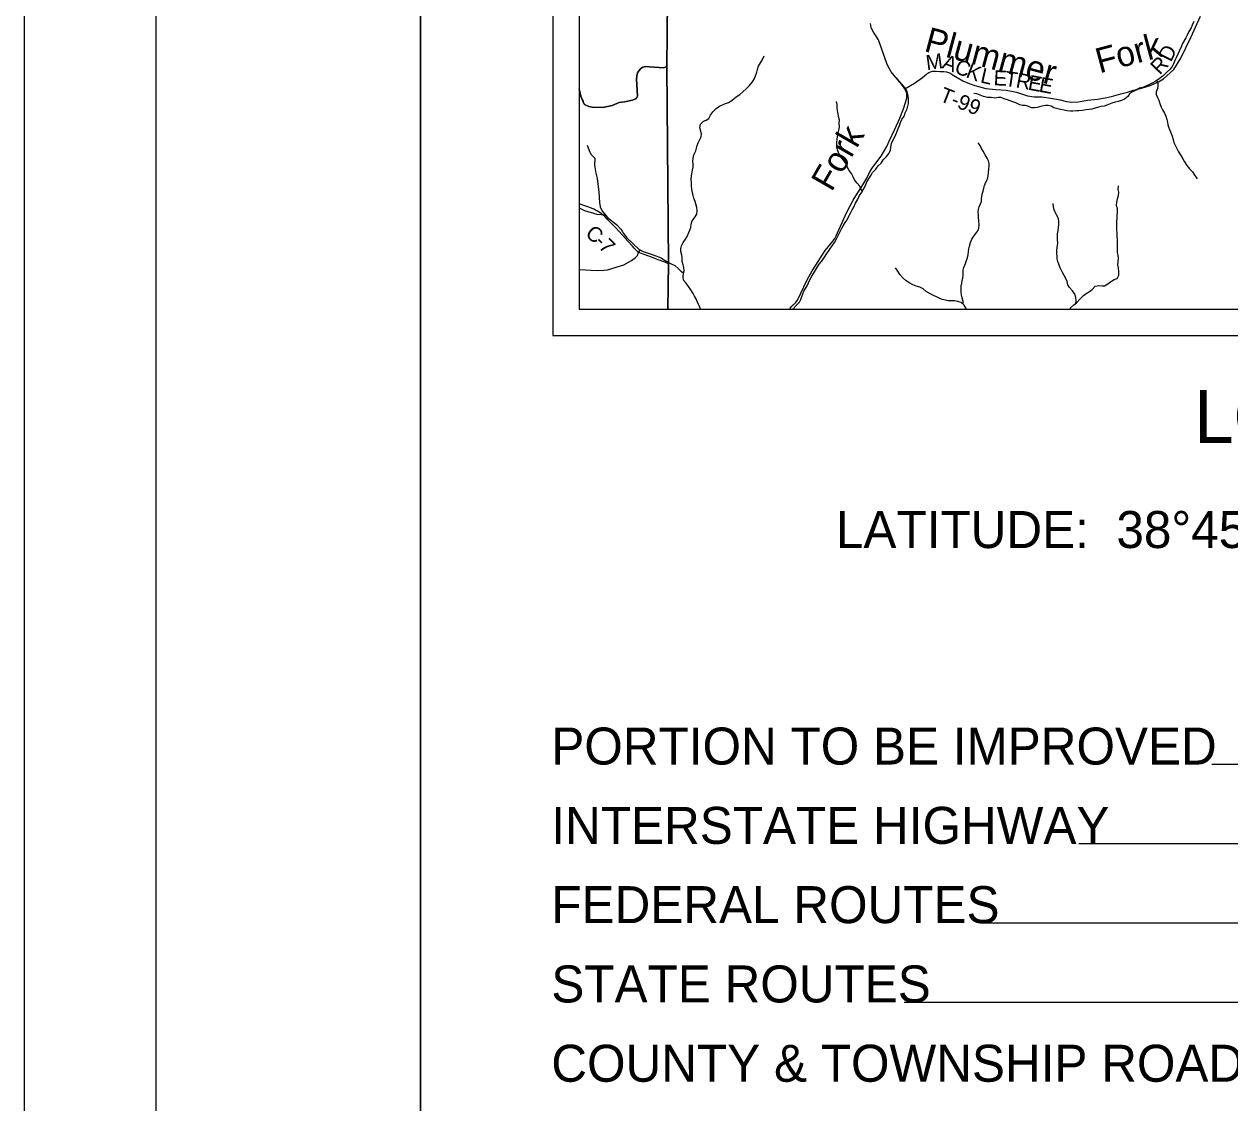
# Model space of a CAD drawing. Extents: x 0 to 34, y 0 to 22.
# Drawn here: x 0 to 4.561, y 11.097 to 15.178 of the extents above; entities that cross this region are included whole.
import ezdxf

# ---------------------------------------------------------------- set-up
doc = ezdxf.new("R2010")
doc.units = 0
for name, color, linetype in [('Default', 7, 'Continuous'), ('GM_X_County_Road', 7, 'Continuous'), ('GM_X_County_Road_Text', 7, 'Continuous'), ('GM_X_Minor_River', 7, 'Continuous'), ('GM_X_Minor_River_Text', 7, 'Continuous'), ('GM_X_Township_Road', 7, 'Continuous'), ('GM_X_Township_Road_Text', 7, 'Continuous'), ('SH_Border', 7, 'Continuous'), ('SH_Cut_Line', 7, 'Continuous'), ('SH_Data', 7, 'Continuous'), ('SH_Text', 7, 'Continuous')]:
    doc.layers.add(name, color=color, linetype=linetype)

msp = doc.modelspace()

# ---------------------------------------------------------------- linework, layer by layer
at = {"layer": 'Default'}
for points in [[(2.1, 20.9), (2.1, 14.9328), (2.1059, 14.9055), (2.1107, 14.8926), (2.1145, 14.8869), (2.1149, 14.8831), (2.1198, 14.8743), (2.1368, 14.8662), (2.1494, 14.8639), (2.1897, 14.8632), (2.2247, 14.8702), (2.251, 14.8811), (2.2715, 14.8844), (2.3013, 14.8899), (2.3142, 14.8956), (2.3184, 14.9005), (2.32, 14.905), (2.318, 14.9497), (2.3165, 14.9685), (2.3178, 14.9818), (2.3209, 14.9936), (2.3258, 15.0011), (2.3335, 15.0098), (2.3411, 15.0151), (2.351, 15.0173), (2.3658, 15.0169), (2.4195, 15.0127), (2.4254, 15.0155), (2.4313, 15.0183), (2.4545, 17.2795)], [(2.4545, 17.2795), (2.4313, 15.0183), (2.4372, 14.2719), (2.4352, 14.1), (8.9, 14.1), (8.9, 18.9397)]]:
    msp.add_lwpolyline(points, dxfattribs=at)
msp.add_lwpolyline([(2.1, 14.9328), (2.1, 14.1), (2.4352, 14.1), (2.4372, 14.2719), (2.4313, 15.0183), (2.4254, 15.0155), (2.4195, 15.0127), (2.3658, 15.0169), (2.351, 15.0173), (2.3411, 15.0151), (2.3335, 15.0098), (2.3258, 15.0011), (2.3209, 14.9936), (2.3178, 14.9818), (2.3165, 14.9685), (2.318, 14.9497), (2.32, 14.905), (2.3184, 14.9005), (2.3142, 14.8956), (2.3013, 14.8899), (2.2715, 14.8844), (2.251, 14.8811), (2.2247, 14.8702), (2.1897, 14.8632), (2.1494, 14.8639), (2.1368, 14.8662), (2.1198, 14.8743), (2.1149, 14.8831), (2.1145, 14.8869), (2.1107, 14.8926), (2.1059, 14.9055)], close=True, dxfattribs=at)
at = {"layer": 'GM_X_County_Road'}
for points in [[(2.8964, 14.1), (2.8985, 14.103), (2.9047, 14.1105), (2.9197, 14.1252), (2.9257, 14.1339), (2.962, 14.2104), (2.9811, 14.2452), (2.9956, 14.2664), (3.0302, 14.3217), (3.0591, 14.3569), (3.0665, 14.3668), (3.0716, 14.3775), (3.1108, 14.4635), (3.1369, 14.5123), (3.1467, 14.5285), (3.1555, 14.5428), (3.169, 14.5632), (3.1879, 14.5955), (3.198, 14.6163), (3.2074, 14.6319), (3.2423, 14.6779), (3.2633, 14.7145), (3.2723, 14.7358), (3.2938, 14.7807), (3.3124, 14.8221), (3.3262, 14.8571), (3.3343, 14.8812), (3.3389, 14.8979), (3.3396, 14.9032), (3.3396, 14.9091), (3.3391, 14.9139), (3.3385, 14.9191), (3.3323, 14.9337), (3.3233, 14.9462), (3.3064, 14.9662), (3.291, 14.9837), (3.2801, 14.9979), (3.2738, 15.0088), (3.2652, 15.0259), (3.2465, 15.0797), (3.2327, 15.118), (3.2237, 15.1331), (3.2136, 15.1482), (3.2081, 15.157), (3.2043, 15.1658), (3.2013, 15.1804)], [(2.4374, 14.2714), (2.4241, 14.2775), (2.399, 14.2868), (2.3733, 14.2958), (2.3315, 14.3118), (2.3264, 14.3141), (2.3232, 14.3159), (2.3203, 14.3181), (2.3172, 14.321), (2.3134, 14.3251), (2.3082, 14.331), (2.3018, 14.3382), (2.2842, 14.3565), (2.2644, 14.3778), (2.2496, 14.3951), (2.24, 14.4057), (2.2287, 14.4172), (2.2139, 14.4315), (2.2053, 14.4403), (2.1969, 14.4497), (2.1843, 14.4602), (2.1755, 14.4664), (2.1685, 14.4708), (2.1617, 14.4745), (2.1548, 14.4777), (2.146, 14.4813), (2.132, 14.4864), (2.1218, 14.4901), (2.1, 14.4984)]]:
    msp.add_lwpolyline(points, dxfattribs=at)
at = {"layer": 'GM_X_Minor_River'}
for points in [[(4.4246, 15.1877), (4.4185, 15.1741), (4.4146, 15.1646), (4.4062, 15.1502), (4.3996, 15.1362), (4.395, 15.1264), (4.3827, 15.1052), (4.3781, 15.0946), (4.3707, 15.0779), (4.365, 15.0643), (4.3576, 15.0503), (4.3526, 15.04), (4.3476, 15.0279), (4.343, 15.0181), (4.3353, 15.0071), (4.3208, 14.9939), (4.3086, 14.9818), (4.294, 14.9709), (4.2811, 14.9622), (4.2673, 14.9543), (4.2574, 14.949), (4.2441, 14.9427), (4.2323, 14.9382), (4.2201, 14.9356), (4.2063, 14.9285), (4.193, 14.9213), (4.1823, 14.9142), (4.1754, 14.9036), (4.1632, 14.8945), (4.1514, 14.8897), (4.1388, 14.8859), (4.1278, 14.8826), (4.1152, 14.8792), (4.0965, 14.871), (4.0862, 14.8676), (4.0744, 14.8662), (4.0645, 14.8639), (4.0512, 14.8598), (4.039, 14.8561)], [(2.6053, 14.8462), (2.6176, 14.8583), (2.6306, 14.8677), (2.6439, 14.8736), (2.6538, 14.8781), (2.6641, 14.8815), (2.6778, 14.889), (2.6873, 14.8973), (2.6976, 14.9056), (2.7072, 14.9112), (2.7194, 14.9225), (2.7312, 14.9331), (2.7442, 14.9459), (2.755, 14.9591), (2.7634, 14.9727), (2.7681, 14.9864), (2.7716, 14.9962), (2.7747, 15.0064), (2.7782, 15.0193), (2.7862, 15.0322), (2.7932, 15.0447), (2.7997, 15.0579)], [(2.909, 14.1), (2.9093, 14.1008), (2.9212, 14.1133), (2.9338, 14.1261), (2.9384, 14.1367), (2.9427, 14.1473), (2.9462, 14.1572), (2.9497, 14.1674), (2.9562, 14.1776), (2.962, 14.1875), (2.9674, 14.1988), (2.9724, 14.2109), (2.9797, 14.2246), (2.9859, 14.2344), (2.9932, 14.2472), (3.0012, 14.2597), (3.0081, 14.2696), (3.0166, 14.2805), (3.0284, 14.2968), (3.0373, 14.3108), (3.0484, 14.3266), (3.0565, 14.3395), (3.0653, 14.352), (3.0734, 14.3652), (3.0799, 14.3781), (3.0857, 14.3909), (3.0926, 14.4038), (3.0988, 14.4144), (3.1061, 14.4269), (3.113, 14.4382), (3.1203, 14.4515), (3.1265, 14.4632), (3.1327, 14.4753), (3.1388, 14.4859), (3.1457, 14.5003), (3.1523, 14.5139), (3.1608, 14.5294), (3.1692, 14.5423), (3.1769, 14.5567), (3.1827, 14.568), (3.1881, 14.5809), (3.1973, 14.5953), (3.2039, 14.6066), (3.2092, 14.6168), (3.2226, 14.6297), (3.2303, 14.6418), (3.2425, 14.6519), (3.2498, 14.6644), (3.2621, 14.6772), (3.2724, 14.6893), (3.2774, 14.7014), (3.2783, 14.7121), (3.2814, 14.7265), (3.2872, 14.7401), (3.2934, 14.7522), (3.3011, 14.7689), (3.3069, 14.7837), (3.3111, 14.7943), (3.3154, 14.806), (3.32, 14.8174), (3.3293, 14.8298), (3.3331, 14.8424), (3.3401, 14.8579), (3.3436, 14.8677), (3.3459, 14.878), (3.346, 14.8882), (3.3453, 14.8981), (3.3428, 14.9114), (3.3391, 14.9255), (3.3312, 14.9377), (3.3203, 14.9503), (3.3101, 14.9625), (3.3007, 14.9747)], [(4.2847, 14.9647), (4.2886, 14.9534), (4.2889, 14.9436), (4.2874, 14.9341), (4.2823, 14.9216), (4.2827, 14.9121), (4.2879, 14.8999), (4.2924, 14.8904), (4.2961, 14.8782), (4.3021, 14.8641), (4.307, 14.8538), (4.3138, 14.8416), (4.3186, 14.8295), (4.3223, 14.8169), (4.3249, 14.8074), (4.3272, 14.7971), (4.3301, 14.7861), (4.3391, 14.7648), (4.3429, 14.7541), (4.3466, 14.7412), (4.3499, 14.7302), (4.3559, 14.718), (4.3612, 14.7081), (4.3676, 14.6948), (4.3762, 14.6814), (4.3834, 14.6685), (4.3894, 14.6574), (4.398, 14.6429), (4.4082, 14.6303), (4.4196, 14.6189), (4.4293, 14.6052), (4.4372, 14.5922)], [(3.171, 14.5457), (3.1659, 14.5549), (3.161, 14.5644), (3.152, 14.5766), (3.1419, 14.5884), (3.1366, 14.6006), (3.1295, 14.6128), (3.1213, 14.6247), (3.1145, 14.6361), (3.1093, 14.6494), (3.0999, 14.6639), (3.0894, 14.6765), (3.0827, 14.6887), (3.0767, 14.7024), (3.0741, 14.7154), (3.075, 14.7298), (3.0759, 14.7431), (3.0771, 14.7526), (3.0798, 14.7662), (3.0822, 14.7768), (3.0846, 14.789), (3.0835, 14.803), (3.084, 14.8148), (3.0811, 14.8289), (3.0792, 14.8388), (3.0774, 14.8517), (3.0764, 14.8612), (3.0753, 14.8734), (3.0728, 14.8859)], [(4.039, 14.8561), (4.0287, 14.8547), (4.0162, 14.8536), (4.0044, 14.8518), (3.9903, 14.8499), (3.9808, 14.8496), (3.9679, 14.8482), (3.9584, 14.8482), (3.9451, 14.8502), (3.9341, 14.8525), (3.9204, 14.8556), (3.9105, 14.858), (3.8957, 14.8619), (3.8851, 14.8672), (3.8741, 14.8696), (3.8639, 14.8704), (3.8502, 14.8682), (3.8327, 14.863), (3.8224, 14.8608), (3.8106, 14.8608), (3.7977, 14.8677), (3.7871, 14.8701), (3.7768, 14.8705), (3.767, 14.8728), (3.7522, 14.8805), (3.7405, 14.8836), (3.7302, 14.8882), (3.7199, 14.8913), (3.7074, 14.896), (3.6949, 14.9002), (3.6854, 14.8999), (3.6728, 14.8981), (3.6588, 14.9), (3.644, 14.9009), (3.6292, 14.904), (3.6166, 14.9094), (3.6045, 14.9148), (3.5927, 14.9152)], [(2.5585, 14.1), (2.5583, 14.1006), (2.5531, 14.1131), (2.5486, 14.1227), (2.5434, 14.136), (2.5367, 14.149), (2.531, 14.1585), (2.522, 14.1722), (2.5134, 14.1852), (2.504, 14.1978), (2.4939, 14.2096), (2.4928, 14.2222), (2.4944, 14.2355), (2.4968, 14.2449), (2.4954, 14.2575), (2.4928, 14.2674), (2.4899, 14.2803), (2.4896, 14.2947), (2.4878, 14.3042), (2.4848, 14.3172), (2.4849, 14.3297), (2.4865, 14.3392), (2.4938, 14.3517), (2.5023, 14.3642), (2.5088, 14.3747), (2.515, 14.3891), (2.5185, 14.399), (2.5216, 14.4092), (2.5239, 14.421), (2.5278, 14.4339), (2.5367, 14.4456), (2.5447, 14.4592), (2.5467, 14.474), (2.5449, 14.4839), (2.542, 14.4934), (2.5383, 14.5071), (2.5338, 14.5197), (2.5305, 14.5299), (2.5279, 14.5414), (2.5261, 14.5528), (2.5247, 14.568), (2.5244, 14.5778), (2.523, 14.5908), (2.5246, 14.6044), (2.5285, 14.6249), (2.5309, 14.6363), (2.5306, 14.6469), (2.5299, 14.6595), (2.5304, 14.6697), (2.5335, 14.6834), (2.5405, 14.6989), (2.544, 14.7091), (2.5467, 14.7194), (2.5502, 14.7288), (2.5552, 14.739), (2.5614, 14.7512), (2.5626, 14.7614), (2.5596, 14.7732), (2.5567, 14.7861), (2.5591, 14.7994), (2.5702, 14.8107), (2.5797, 14.8148), (2.59, 14.8208), (2.5969, 14.8333), (2.6053, 14.8462)], [(2.13, 14.7195), (2.1404, 14.6932), (2.1457, 14.6849), (2.1592, 14.6708), (2.1579, 14.6446), (2.163, 14.6138), (2.1678, 14.5941), (2.1743, 14.5417), (2.1764, 14.5026), (2.1789, 14.4863), (2.1871, 14.4703), (2.2074, 14.4463), (2.2406, 14.4195), (2.2568, 14.4027), (2.2624, 14.3944), (2.268, 14.386), (2.2804, 14.37), (2.3271, 14.3253), (2.3422, 14.3173), (2.3762, 14.3069), (2.4102, 14.2934), (2.4307, 14.2798)], [(3.5522, 14.1188), (3.5528, 14.1286), (3.5491, 14.1419), (3.5457, 14.1537), (3.5454, 14.164), (3.5443, 14.1754), (3.5455, 14.1864), (3.5475, 14.1978), (3.5487, 14.208), (3.5507, 14.2175), (3.5519, 14.2274), (3.5528, 14.2471), (3.5544, 14.257), (3.5617, 14.2721), (3.5679, 14.2911), (3.571, 14.3055), (3.5722, 14.3184), (3.5738, 14.3279), (3.5758, 14.3377), (3.5801, 14.3514), (3.5858, 14.365), (3.5928, 14.3756), (3.6, 14.3862), (3.6073, 14.396), (3.6112, 14.4055), (3.6128, 14.4192), (3.6114, 14.434), (3.6103, 14.4465), (3.61, 14.4564), (3.6089, 14.4663), (3.6109, 14.4773), (3.6136, 14.4868), (3.6175, 14.4977), (3.6213, 14.5076), (3.6222, 14.5175), (3.6249, 14.5345), (3.628, 14.5467), (3.63, 14.5573), (3.6327, 14.5679), (3.6385, 14.5804), (3.6443, 14.5918), (3.647, 14.6047), (3.6486, 14.6164), (3.6499, 14.6301), (3.6511, 14.6403), (3.6508, 14.6506), (3.6485, 14.6609), (3.6433, 14.6704), (3.6361, 14.6837), (3.6275, 14.6978), (3.6222, 14.7073), (3.6166, 14.7191), (3.6091, 14.7287)], [(3.9554, 14.1), (3.9578, 14.1039), (3.9705, 14.1156), (3.9811, 14.1231), (3.9946, 14.139), (4.0079, 14.1515), (4.0175, 14.1586), (4.0308, 14.1669), (4.0404, 14.1741), (4.0523, 14.1862), (4.0652, 14.1887), (4.0777, 14.1883), (4.0876, 14.1879), (4.1002, 14.1954), (4.1101, 14.2029), (4.1235, 14.212), (4.1353, 14.2161), (4.1411, 14.2286), (4.1419, 14.2415), (4.1398, 14.2555), (4.1379, 14.2677), (4.1391, 14.2791), (4.14, 14.292), (4.1385, 14.3045), (4.1367, 14.3144), (4.136, 14.3251), (4.1365, 14.338), (4.1366, 14.352), (4.1362, 14.3615), (4.1352, 14.3756), (4.1353, 14.3877), (4.1334, 14.3999), (4.1339, 14.4101), (4.1343, 14.4223), (4.134, 14.4318), (4.1349, 14.4447), (4.1349, 14.4546), (4.1358, 14.4659), (4.1366, 14.4792), (4.1329, 14.4914), (4.1337, 14.5047), (4.1369, 14.5176), (4.1396, 14.5297), (4.1412, 14.5426), (4.1382, 14.5525), (4.1402, 14.5658)], [(2.1, 14.483), (2.1027, 14.4814), (2.1197, 14.4733), (2.167, 14.459), (2.1988, 14.4565)], [(3.9787, 14.1214), (3.9793, 14.1311), (3.979, 14.1444), (3.9753, 14.1566), (3.9659, 14.1692), (3.9553, 14.1818), (3.9485, 14.1921), (3.9456, 14.2042), (3.9403, 14.2157), (3.9347, 14.2271), (3.9268, 14.2412), (3.9197, 14.256), (3.914, 14.2697), (3.9111, 14.2804), (3.9081, 14.2903), (3.9078, 14.3001), (3.9067, 14.3112), (3.9068, 14.3222), (3.908, 14.3332), (3.91, 14.3499), (3.9097, 14.3628), (3.909, 14.3731), (3.9098, 14.3848), (3.9118, 14.3977), (3.9127, 14.4091), (3.9139, 14.4194), (3.9139, 14.4296), (3.9132, 14.4429), (3.9053, 14.4562), (3.9005, 14.4665), (3.896, 14.4791), (3.8938, 14.4886), (3.8931, 14.4988)], [(2.1, 14.2495), (2.1005, 14.2496), (2.1683, 14.2465), (2.1929, 14.2468), (2.2066, 14.2486), (2.2688, 14.2676), (2.2977, 14.2838), (2.3133, 14.2947), (2.3205, 14.303), (2.3232, 14.3113), (2.3301, 14.3237)], [(2.4943, 14.2344), (2.4858, 14.242), (2.4745, 14.2538), (2.4624, 14.2638), (2.4488, 14.27), (2.4367, 14.2765), (2.4307, 14.2798)], [(3.4124, 14.1661), (3.4013, 14.176), (3.3888, 14.183), (3.3752, 14.1869), (3.362, 14.1916), (3.3506, 14.1977), (3.3374, 14.2065), (3.3242, 14.2176), (3.3133, 14.2303), (3.3047, 14.244), (3.2964, 14.2554)], [(3.5654, 14.1), (3.5644, 14.102), (3.5565, 14.1149), (3.5455, 14.1249), (3.5326, 14.1291), (3.5193, 14.1307), (3.4962, 14.1308), (3.4859, 14.1332), (3.4726, 14.1359), (3.4597, 14.142), (3.4355, 14.1543), (3.4124, 14.1661)]]:
    msp.add_lwpolyline(points, dxfattribs=at)
at = {"layer": 'GM_X_Township_Road'}
msp.add_lwpolyline([(3.3323, 14.9337), (3.3687, 14.9541), (3.3987, 14.9761), (3.4147, 14.9905), (3.4228, 14.9953), (3.4286, 14.9976), (3.4358, 15.0004), (3.4442, 15.0006), (3.4503, 14.9998), (3.464, 14.9992), (3.4798, 14.9985), (3.4894, 14.9971), (3.4971, 14.995), (3.5047, 14.9922), (3.5111, 14.9875), (3.551, 14.9632), (3.5756, 14.9528), (3.597, 14.9459), (3.6386, 14.934), (3.6763, 14.9302), (3.7155, 14.9281), (3.7356, 14.9246), (3.754, 14.92), (3.7952, 14.907), (3.821, 14.903), (3.8495, 14.9025), (3.884, 14.8978), (3.9191, 14.8914), (3.9433, 14.8857), (3.963, 14.8827), (3.9893, 14.8837), (4.0229, 14.8903), (4.0604, 14.8947), (4.0898, 14.8988), (4.1132, 14.9043), (4.1483, 14.9138), (4.1741, 14.9212), (4.193, 14.9265), (4.2277, 14.9357), (4.2598, 14.9457), (4.2909, 14.9598), (4.3109, 14.9715), (4.3495, 15.0058), (4.3758, 15.0497), (4.4135, 15.127), (4.4497, 15.2084)], dxfattribs=at)
at = {"layer": 'SH_Border'}
for points in [[(0.5, 21.5), (1.5, 21.5), (1.5, 0.5), (0.5, 0.5)], [(1.5, 21.5), (33.5, 21.5), (33.5, 0.5), (1.5, 0.5)]]:
    msp.add_lwpolyline(points, close=True, dxfattribs=at)
at = {"layer": 'SH_Cut_Line'}
for points in [[(0, 0), (34, 0), (34, 22), (0, 22)], [(2.4845, 20.9), (2.1, 20.9), (2.1, 14.1), (2.4352, 14.1), (2.4372, 14.2719), (2.4313, 15.0183), (2.4545, 17.2795), (2.4586, 17.7785), (2.4581, 18.1772), (2.4581, 18.1825), (2.4573, 18.9074), (2.4757, 20.2566), (2.4809, 20.6393)], [(2.4352, 14.1), (8.9, 14.1), (8.9, 20.9), (2.4845, 20.9), (2.4809, 20.6393), (2.4757, 20.2566), (2.4573, 18.9074), (2.4581, 18.1825), (2.4581, 18.1772), (2.4586, 17.7785), (2.4545, 17.2795), (2.4313, 15.0183), (2.4372, 14.2719)]]:
    msp.add_lwpolyline(points, close=True, dxfattribs=at)
at = {"layer": 'SH_Data'}
for p, q in [((2, 21), (2, 14)), ((2.1, 20.9), (2.1, 14.1)), ((2.1, 14.1), (8.9, 14.1)), ((2.1, 14.1), (2.1, 14.1)), ((2, 14), (9, 14)), ((7.7, 12.3767), (4.4937, 12.3767)), ((7.7, 12.0767), (3.9895, 12.0767)), ((7.7, 11.7767), (3.6192, 11.7767)), ((7.7, 11.4767), (3.3288, 11.4767))]:
    msp.add_line(p, q, dxfattribs=at)

# ---------------------------------------------------------------- texts
at = {"layer": 'GM_X_County_Road_Text'}
for s, rotation, p in [('C', 321.1415, (2.1194, 14.3786)), ('7', 313.5307, (2.1709, 14.3342)), ('-', 315.2056, (2.1546, 14.3503))]:
    msp.add_text(s, height=0.0568, rotation=rotation, dxfattribs=at).set_placement(p)
at = {"layer": 'GM_X_Minor_River_Text'}
for s, height, rotation, p in [('Plummer', 0.09469, 345.0002, (3.4009, 15.0768)), ('Fork', 0.09469, 15.0019, (4.0682, 14.9913)), ('Fork', 0.0947, 60.0008, (3.0548, 14.5406))]:
    msp.add_text(s, height=height, rotation=rotation, dxfattribs=at).set_placement(p)
at = {"layer": 'GM_X_Township_Road_Text'}
for s, height, rotation, p in [('M', 0.0568, 7.4939, (3.4151, 15.0037)), ('A', 0.0568, 339.7032, (3.4691, 15.0126)), ('D', 0.0568, 62.9204, (4.3383, 15.0317)), ('C', 0.0568, 338.769, (3.5158, 14.9953)), ('K', 0.0568, 338.9116, (3.5594, 14.9784)), ('L', 0.0568, 347.2825, (3.6147, 14.9577)), ('R', 0.0568, 46.3221, (4.2958, 14.9836)), ('E', 0.0568, 356.9547, (3.6665, 14.947)), ('T', 0.0568, 351.8341, (3.7077, 14.9448)), ('R', 0.0568, 349.6833, (3.7492, 14.9389)), ('E', 0.0568, 349.5255, (3.795, 14.9305)), ('E', 0.0568, 349.5258, (3.8368, 14.9228)), ('T-99', 0.05682, 338.5868, (3.4594, 14.8884))]:
    msp.add_text(s, height=height, rotation=rotation, dxfattribs=at).set_placement(p)
at = {"layer": 'SH_Text'}
for s, height, p in [('LOCATION MAP', 0.2, (4.4269, 13.5938)), ('LATITUDE:  38°45\'21"     LONGITUDE:  -83°16\'6"', 0.14, (3.071, 13.1959)), ('PORTION TO BE IMPROVED', 0.14, (1.9944, 12.3767)), ('INTERSTATE HIGHWAY', 0.14, (1.9944, 12.0767)), ('FEDERAL ROUTES', 0.14, (1.9944, 11.7767)), ('STATE ROUTES', 0.14, (1.9944, 11.4767)), ('COUNTY & TOWNSHIP ROADS', 0.14, (1.9944, 11.1767))]:
    msp.add_text(s, height=height, dxfattribs=at).set_placement(p)

doc.saveas('drawing.dxf')
